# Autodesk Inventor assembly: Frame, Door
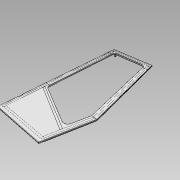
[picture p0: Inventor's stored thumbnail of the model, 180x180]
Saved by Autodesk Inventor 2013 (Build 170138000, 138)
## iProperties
Created: 2012-10
Part Number: Frame, Door
Document SubType Name: Weldment
Designer: VMuser
Weld Material: Welded Aluminum-6061
Author: VMuser
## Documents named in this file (20)
- Y:\Dropbox\Launch 2013\Eco Material Advisor\Assy, Door\_Data\Assy, Cab\Frame, Door.iam
- Y:\Dropbox\Launch 2013\Eco Material Advisor\Assy, Door\_Data\Assy, Cab\PK46.51.11.011.ipt
- Y:\Dropbox\Launch 2013\Eco Material Advisor\Assy, Door\_Data\Assy, Cab\PK46.51.11.014.ipt
- Y:\Dropbox\Launch 2013\Eco Material Advisor\Assy, Door\_Data\Assy, Cab\PK46.51.11.013.ipt
- Y:\Dropbox\Launch 2013\Eco Material Advisor\Assy, Door\_Data\Assy, Cab\PK46.51.11.021.ipt
- Y:\Dropbox\Launch 2013\Eco Material Advisor\Assy, Door\_Data\Assy, Cab\PK46.51.11.023.ipt
- Y:\Dropbox\Launch 2013\Eco Material Advisor\Assy, Door\_Data\Assy, Cab\PK46.51.11.025.ipt
- Y:\Dropbox\Launch 2013\Eco Material Advisor\Assy, Door\_Data\Assy, Cab\PK46.51.11.024.ipt
- Y:\Dropbox\Launch 2013\Eco Material Advisor\Assy, Door\_Data\Assy, Cab\PK46.51.11.031.ipt
- Y:\Dropbox\Launch 2013\Eco Material Advisor\Assy, Door\_Data\Assy, Cab\PK46.51.11.033.ipt
- Y:\Dropbox\Launch 2013\Eco Material Advisor\Assy, Door\_Data\Assy, Cab\PK46.51.11.035.ipt
- Y:\Dropbox\Launch 2013\Eco Material Advisor\Assy, Door\_Data\Assy, Cab\PK46.51.11.034.ipt
- Y:\Dropbox\Launch 2013\Eco Material Advisor\Assy, Door\_Data\Assy, Cab\PK46.51.11.022.ipt
- Y:\Dropbox\Launch 2013\Eco Material Advisor\Assy, Door\_Data\Assy, Cab\PK46.51.11.032.ipt
- Y:\Dropbox\Launch 2013\Eco Material Advisor\Assy, Door\_Data\Assy, Cab\Support gas.ipt
- Y:\Dropbox\Launch 2013\Eco Material Advisor\Assy, Door\_Data\Assy, Cab\PK46.51.11.026.ipt
- Y:\Dropbox\Launch 2013\Eco Material Advisor\Assy, Door\_Data\Assy, Cab\PK46.51.11.016-01.ipt
- Y:\Dropbox\Launch 2013\Eco Material Advisor\Assy, Door\_Data\Assy, Cab\PK46.51.11.016.ipt
- Y:\Dropbox\Launch 2013\Eco Material Advisor\Assy, Door\_Data\Assy, Cab\PK46.51.11.012(new).ipt
- Y:\Dropbox\Launch 2013\Eco Material Advisor\Assy, Door\_Data\Assy, Cab\Frame, Door (Shrinkwrap).ipt
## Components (19 placed, 19 different names)
1. PK46.51.11.011:1
2. PK46.51.11.014:1
3. PK46.51.11.013:1
4. PK46.51.11.021:1
5. PK46.51.11.023:1
6. PK46.51.11.025:1
7. PK46.51.11.024:1
8. PK46.51.11.031:1
9. PK46.51.11.033:1
10. PK46.51.11.035:1
11. PK46.51.11.034:1
12. PK46.51.11.022:1
13. PK46.51.11.032:1
14. Support gas:1
15. PK46.51.11.026:1
16. PK46.51.11.016-01:1
17. PK46.51.11.016:1
18. PK46.51.11.012(new):1
19. Frame, Door (Shrinkwrap):1
## Named parameters: d6_d11 = 0
